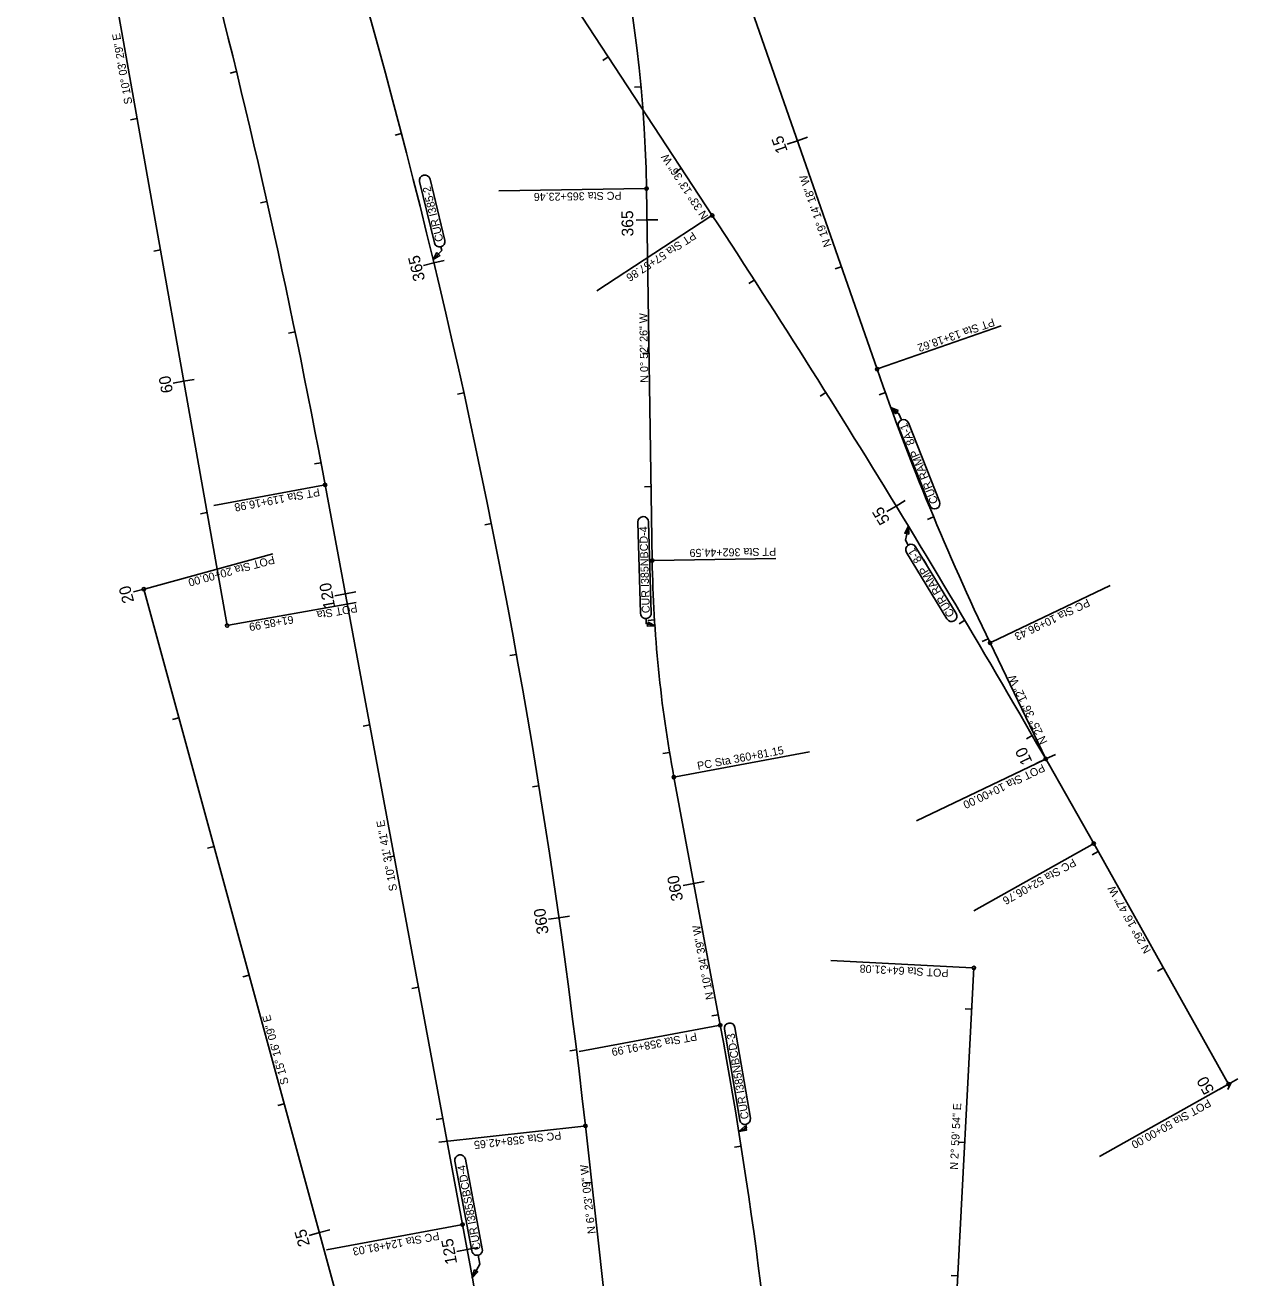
# Model space of a CAD drawing. Extents: x 1603540 to 1622629, y 1083934 to 1103503.
# Drawn here: x 1611940 to 1612849, y 1090133 to 1091073 of the extents above; entities that cross this region are included whole.
import ezdxf

# ---------------------------------------------------------------- set-up
doc = ezdxf.new("R2010")
doc.units = 0
for name, color, linetype in [('RD_EX_BldgChurch', 7, 'Continuous'), ('RD_EX_Fence_ChLk', 7, 'Continuous'), ('RD_EX_H2O', 7, 'Continuous'), ('RD_EX_Misc', 7, 'Continuous'), ('RD_HC_CL', 7, 'Continuous'), ('RD_PG_GR', 7, 'Continuous')]:
    doc.layers.add(name, color=color, linetype=linetype)

msp = doc.modelspace()

# ---------------------------------------------------------------- linework, layer by layer
at = {"layer": 'RD_EX_BldgChurch'}
for p, q in [((1612404.05, 1090950.16), (1612294.6, 1090948.49)), ((1612453.5, 1090929.46), (1612367.96, 1090873.43)), ((1612579.26, 1090815.22), (1612671.18, 1090847.3)), ((1612163.2, 1090727.76), (1612080.98, 1090712.48)), ((1612029.7, 1090650.19), (1612125.34, 1090676.3)), ((1612410.8, 1090671.36), (1612502.2, 1090672.75)), ((1612663.91, 1090610.06), (1612752.77, 1090652.64)), ((1612092.14, 1090622.83), (1612187.8, 1090639.8)), ((1612427.06, 1090509.14), (1612527.52, 1090527.9)), ((1612703.33, 1090522.02), (1612607.65, 1090476.17)), ((1612739.32, 1090458.5), (1612650.65, 1090408.78)), ((1612649.36, 1090365.98), (1612543.35, 1090371.53)), ((1612459.33, 1090322.73), (1612354.87, 1090303.22)), ((1612840.44, 1090278.16), (1612744.76, 1090224.51)), ((1612358.27, 1090247.29), (1612249.66, 1090235.14)), ((1612266.27, 1090173.2), (1612165.56, 1090154.48))]:
    msp.add_line(p, q, dxfattribs=at)
for centre in [(1612405.3, 1090950.18), (1612454.55, 1090930.14), (1612578.08, 1090814.81), (1612164.43, 1090727.99), (1612409.55, 1090671.34), (1612028.5, 1090649.86), (1612090.91, 1090622.61), (1612662.78, 1090609.52), (1612704.46, 1090522.56), (1612425.83, 1090508.91), (1612740.41, 1090459.11), (1612650.6, 1090365.91), (1612460.56, 1090322.96), (1612841.53, 1090278.77), (1612359.51, 1090247.43), (1612267.5, 1090173.43)]:
    msp.add_circle(centre, 1.25, dxfattribs=at)
at = {"layer": 'RD_EX_H2O'}
for p, q in [((1612376.66, 1091049.05), (1612372.48, 1091046.31)), ((1612098.03, 1091037.89), (1612093.17, 1091036.71)), ((1612401.2, 1091026.59), (1612396.22, 1091026.13)), ((1612023.49, 1091002.67), (1612018.57, 1091001.8)), ((1612221.64, 1090991.47), (1612216.8, 1090990.21)), ((1612518.32, 1090986.06), (1612510.77, 1090983.42)), ((1612518.32, 1090986.06), (1612525.87, 1090988.69)), ((1612431.45, 1090965.4), (1612427.27, 1090962.66)), ((1612120.81, 1090940.52), (1612115.93, 1090939.42)), ((1612405.65, 1090926.72), (1612397.65, 1090926.6)), ((1612405.65, 1090926.72), (1612413.65, 1090926.84)), ((1612040.96, 1090904.21), (1612036.04, 1090903.34)), ((1612245.95, 1090894.47), (1612253.73, 1090896.34)), ((1612245.95, 1090894.47), (1612238.17, 1090892.6)), ((1612551.27, 1090891.64), (1612546.55, 1090889.99)), ((1612486.07, 1090881.63), (1612481.87, 1090878.92)), ((1612141.9, 1090842.77), (1612137, 1090841.76)), ((1612407.18, 1090826.73), (1612402.18, 1090826.66)), ((1612058.42, 1090805.75), (1612050.55, 1090804.35)), ((1612058.42, 1090805.75), (1612066.3, 1090807.14)), ((1612268.41, 1090797.03), (1612263.53, 1090795.95)), ((1612539.74, 1090797.25), (1612535.5, 1090794.59)), ((1612584.3, 1090797.26), (1612579.59, 1090795.56)), ((1612161.31, 1090744.67), (1612156.39, 1090743.75)), ((1612408.7, 1090726.74), (1612403.7, 1090726.67)), ((1612592.34, 1090712.2), (1612585.51, 1090708.04)), ((1612592.34, 1090712.2), (1612599.17, 1090716.37)), ((1612075.89, 1090707.28), (1612070.96, 1090706.41)), ((1612289.02, 1090699.18), (1612284.12, 1090698.19)), ((1612620.47, 1090704.04), (1612615.85, 1090702.11)), ((1612028.5, 1090649.86), (1612036.21, 1090651.97)), ((1612028.5, 1090649.86), (1612020.78, 1090647.75)), ((1612179.6, 1090646.36), (1612171.74, 1090644.9)), ((1612179.6, 1090646.36), (1612187.47, 1090647.82)), ((1612411.26, 1090626.79), (1612406.27, 1090626.48)), ((1612643.88, 1090626.51), (1612639.57, 1090623.96)), ((1612661.24, 1090612.74), (1612656.73, 1090610.59)), ((1612307.77, 1090600.95), (1612302.85, 1090600.06)), ((1612054.83, 1090553.39), (1612050.01, 1090552.07)), ((1612197.87, 1090548.05), (1612192.96, 1090547.13)), ((1612694.34, 1090540.17), (1612690, 1090537.68)), ((1612422.56, 1090527.47), (1612417.62, 1090526.65)), ((1612704.46, 1090522.56), (1612697.24, 1090519.1)), ((1612704.46, 1090522.56), (1612711.67, 1090526.01)), ((1612324.66, 1090502.39), (1612319.73, 1090501.59)), ((1612081.17, 1090456.92), (1612076.34, 1090455.6)), ((1612216.15, 1090449.73), (1612211.23, 1090448.82)), ((1612743.72, 1090453.22), (1612739.35, 1090450.77)), ((1612440.73, 1090429.14), (1612432.87, 1090427.67)), ((1612440.73, 1090429.14), (1612448.6, 1090430.61)), ((1612339.68, 1090403.53), (1612331.76, 1090402.4)), ((1612339.68, 1090403.53), (1612347.6, 1090404.65)), ((1612107.5, 1090360.45), (1612102.68, 1090359.13)), ((1612792.62, 1090365.99), (1612788.26, 1090363.55)), ((1612234.42, 1090351.41), (1612229.5, 1090350.5)), ((1612648.98, 1090334.87), (1612643.99, 1090335.13)), ((1612459.09, 1090330.84), (1612454.17, 1090329.92)), ((1612352.82, 1090304.39), (1612347.86, 1090303.78)), ((1612841.53, 1090278.77), (1612834.55, 1090274.86)), ((1612843.1, 1090279.41), (1612841.02, 1090274.86)), ((1612841.53, 1090278.77), (1612848.51, 1090282.68)), ((1612133.84, 1090263.98), (1612129.01, 1090262.66)), ((1612252.69, 1090253.1), (1612247.77, 1090252.18)), ((1612476.17, 1090232.31), (1612471.23, 1090231.53)), ((1612643.75, 1090235.01), (1612638.75, 1090235.27)), ((1612364.25, 1090205.05), (1612359.28, 1090204.49)), ((1612160.17, 1090167.51), (1612152.45, 1090165.4)), ((1612160.17, 1090167.51), (1612167.89, 1090169.62)), ((1612270.93, 1090154.77), (1612263.06, 1090153.34)), ((1612270.93, 1090154.77), (1612278.8, 1090156.21)), ((1612638.52, 1090135.15), (1612633.52, 1090135.41))]:
    msp.add_line(p, q, dxfattribs=at)
at = {"layer": 'RD_HC_CL'}
for p, q in [((1611969.73, 1091305.79), (1612090.91, 1090622.61)), ((1612578.08, 1090814.81), (1612456.02, 1091164.58)), ((1612454.55, 1090930.14), (1612335.24, 1091112.27)), ((1612409.55, 1090671.34), (1612405.3, 1090950.18)), ((1612164.43, 1090727.99), (1612267.5, 1090173.43)), ((1612028.5, 1090649.86), (1612271.43, 1089759.95)), ((1612704.46, 1090522.56), (1612662.78, 1090609.52)), ((1612460.56, 1090322.96), (1612425.83, 1090508.91)), ((1612841.53, 1090278.77), (1612740.41, 1090459.11)), ((1612608.3, 1089558.32), (1612650.6, 1090365.91)), ((1612510.54, 1088897.98), (1612359.51, 1090247.43))]:
    msp.add_line(p, q, dxfattribs=at)
for centre, radius, start, end in [((1606462.07, 1089668.23), 5800, 10.528082, 19.196724), ((1607115.5, 1089660.54), 5276.75, 6.3858, 20.71665), ((1611405.41, 1090934.93), 1000, 0.87381, 28.55542), ((1605762.47, 1086546.53), 8000, 29.279616, 33.226597), ((1614466.4, 1091473.8), 2000, 199.23822, 205.60342), ((1613374.44, 1090686.06), 965, 180.87381, 190.57758), ((1609241.21, 1089721.78), 3275, 3.27051, 10.57758), ((1606368.5, 1089077.12), 6000, 6.385803, 10.528082)]:
    msp.add_arc(centre, radius, start, end, dxfattribs=at)
at = {"layer": 'RD_PG_GR'}
for p, q in [((1612235.26, 1090955.46), (1612246.34, 1090909.48)), ((1612254.12, 1090911.36), (1612243.04, 1090957.33)), ((1612624.95, 1090715.54), (1612601.54, 1090774.51)), ((1612594.1, 1090771.55), (1612617.51, 1090712.58)), ((1612398.82, 1090700.19), (1612400.79, 1090631.76)), ((1612408.8, 1090631.99), (1612406.82, 1090700.42)), ((1612637.31, 1090631.65), (1612606.99, 1090681.61)), ((1612600.15, 1090677.46), (1612630.47, 1090627.5)), ((1612463.61, 1090319.97), (1612475.21, 1090251.83)), ((1612483.1, 1090253.18), (1612471.51, 1090321.31)), ((1612261.7, 1090221.05), (1612274.37, 1090153.68)), ((1612282.24, 1090155.16), (1612269.56, 1090222.53))]:
    msp.add_line(p, q, dxfattribs=at)
for points in [[(1612251.17, 1090906.53), (1612251.82, 1090903.8), (1612245.35, 1090896.96)], [(1612596.34, 1090776.75), (1612594.5, 1090781.38), (1612588.35, 1090786.1)], [(1612601.5, 1090682.96), (1612599.35, 1090686.49), (1612601.54, 1090697.09)], [(1612404.91, 1090627.87), (1612405.02, 1090624.04), (1612411.84, 1090622.27)], [(1612479.82, 1090248.56), (1612480.25, 1090246.05), (1612474.43, 1090243.27)], [(1612279.05, 1090150.49), (1612280.29, 1090143.91), (1612274.69, 1090133.61)]]:
    msp.add_lwpolyline(points, dxfattribs=at)
for points in [[(1612248.2, 1090902.24), (1612245.35, 1090896.96), (1612250.46, 1090900.1)], [(1612593.89, 1090783.81), (1612588.35, 1090786.1), (1612592, 1090781.34)], [(1612601.89, 1090691.1), (1612601.54, 1090697.09), (1612598.84, 1090691.73)], [(1612405.84, 1090622.22), (1612411.84, 1090622.27), (1612406.62, 1090625.23)], [(1612478.98, 1090247.17), (1612474.43, 1090243.27), (1612480.32, 1090244.37)], [(1612276.09, 1090139.44), (1612274.69, 1090133.61), (1612278.82, 1090137.96)]]:
    msp.add_lwpolyline(points, close=True, dxfattribs=at)
for centre, start, end in [((1612239.15, 1090956.39), 13.55123, 193.55123), ((1612250.23, 1090910.42), 193.55123, 13.55123), ((1612597.82, 1090773.03), 21.65608, 201.65608), ((1612621.23, 1090714.06), 201.65608, 21.65608), ((1612402.82, 1090700.3), 1.65608, 181.65608), ((1612603.57, 1090679.54), 31.25311, 211.25311), ((1612404.79, 1090631.87), 181.65608, 1.65608), ((1612633.89, 1090629.58), 211.25311, 31.25311), ((1612467.56, 1090320.64), 9.65608, 189.65608), ((1612479.15, 1090252.5), 189.65608, 9.65608), ((1612265.63, 1090221.79), 10.65608, 190.65608), ((1612278.31, 1090154.42), 190.65608, 10.65608)]:
    msp.add_arc(centre, 4, start, end, dxfattribs=at)

# ---------------------------------------------------------------- texts
at = {"layer": 'RD_EX_BldgChurch'}
for s, rotation, p in [('PC Sta 365+23.46', 180.87381, (1612386.58, 1090947.89)), ('PT Sta 57+57.86', 213.2266, (1612439.96, 1090918.2)), ('PT Sta 13+18.62', 199.23822, (1612664.91, 1090853.13)), ('PT Sta 119+16.98', 190.52808, (1612159.85, 1090725.72)), ('PT Sta 362+44.59', 180.87381, (1612502.41, 1090680.98)), ('POT Sta 20+00.00', 195.26905, (1612125.68, 1090675.06)), ('PC Sta 10+96.43', 205.60342, (1612735.75, 1090642.97)), ('POT Sta ', 190.05799, (1612188.01, 1090638.65)), ('61+85.99', 190.05799, (1612140.21, 1090630.17)), ('PC Sta 360+81.15', 10.57758, (1612443.9, 1090514.32)), ('POT Sta 10+00.00', 205.60342, (1612702.05, 1090519.11)), ('PC Sta 52+06.76', 209.27962, (1612725.04, 1090448.19)), ('POT Sta 64+31.08', 177.00155, (1612631.78, 1090364.9)), ('PT Sta 358+91.99', 190.57758, (1612442.49, 1090317.55)), ('POT Sta 50+00.00', 209.27962, (1612826.15, 1090267.85)), ('PC Sta 358+42.65', 186.3858, (1612341.1, 1090243.36)), ('PC Sta 124+81.03', 190.52808, (1612249.43, 1090168.03))]:
    msp.add_text(s, height=6, rotation=rotation, dxfattribs=at).set_placement(p)
at = {"layer": 'RD_EX_Fence_ChLk'}
for s, rotation, p in [('S 10%%d 03\' 29" E', 100.05799, (1612020.04, 1091013.96)), ('N 33%%d 13\' 36" W', 123.2266, (1612451.9, 1090929.6)), ('N 19%%d 14\' 18" W', 109.23822, (1612544.03, 1090907.57)), ('N 0%%d 52\' 26" W', 90.87381, (1612406.66, 1090804.69)), ('N 25%%d 36\' 12" W', 115.60342, (1612705.92, 1090535.27)), ('S 10%%d 31\' 41" E', 100.52808, (1612218.53, 1090424.08)), ('N 29%%d 16\' 47" W', 119.27962, (1612783.56, 1090378.85)), ('N 10%%d 34\' 39" W', 100.57758, (1612455.77, 1090342.64)), ('S 15%%d 16\' 09" E', 105.26905, (1612137.24, 1090279.25)), ('N 2%%d 59\' 54" E', 87.00155, (1612638.58, 1090214.5)), ('N 6%%d 23\' 09" W', 96.3858, (1612367.17, 1090166.83))]:
    msp.add_text(s, height=6, rotation=rotation, dxfattribs=at).set_placement(p)
at = {"layer": 'RD_EX_Misc'}
for s, rotation, p in [('15', 109.23822, (1612511.21, 1090978.36)), ('365', 90.87381, (1612395.5, 1090914.36)), ('365', 103.52344, (1612239.46, 1090881.89)), ('60', 100.05799, (1612050.46, 1090797.65)), ('55', 121.37982, (1612588.08, 1090701.42)), ('20', 105.26905, (1612021.41, 1090640.68)), ('120', 100.52808, (1612172.1, 1090636.1)), ('10', 115.60342, (1612694.67, 1090520.6)), ('360', 100.57758, (1612432.79, 1090416.8)), ('360', 98.09436, (1612332.01, 1090391.75)), ('50', 119.27962, (1612831.1, 1090274.2)), ('25', 105.26905, (1612153.13, 1090158.2)), ('125', 100.34696, (1612263.42, 1090144.4))]:
    msp.add_text(s, height=8.75, rotation=rotation, dxfattribs=at).set_placement(p)
at = {"layer": 'RD_PG_GR'}
for s, rotation, p in [('CUR I385-2', 103.55123, (1612253.14, 1090911.12)), ('CUR RAMP_8A-1', 111.65608, (1612624.02, 1090715.17)), ('CUR I385NBCD-4', 91.65608, (1612407.79, 1090631.96)), ('CUR RAMP_8-1', 121.25311, (1612636.46, 1090631.13)), ('CUR I385NBCD-3', 99.65608, (1612482.11, 1090253.01)), ('CUR I385SBCD-4', 100.65608, (1612281.25, 1090154.98))]:
    msp.add_text(s, height=6, rotation=rotation, dxfattribs=at).set_placement(p)

doc.saveas('drawing.dxf')
